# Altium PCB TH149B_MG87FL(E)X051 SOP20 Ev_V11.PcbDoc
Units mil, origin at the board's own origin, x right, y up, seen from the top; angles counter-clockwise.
Board outline 2850 x 2111 mil, 2 copper layers (Top Layer, Bottom Layer); 47 components, 39 nets, 238 pads, 92 vias.
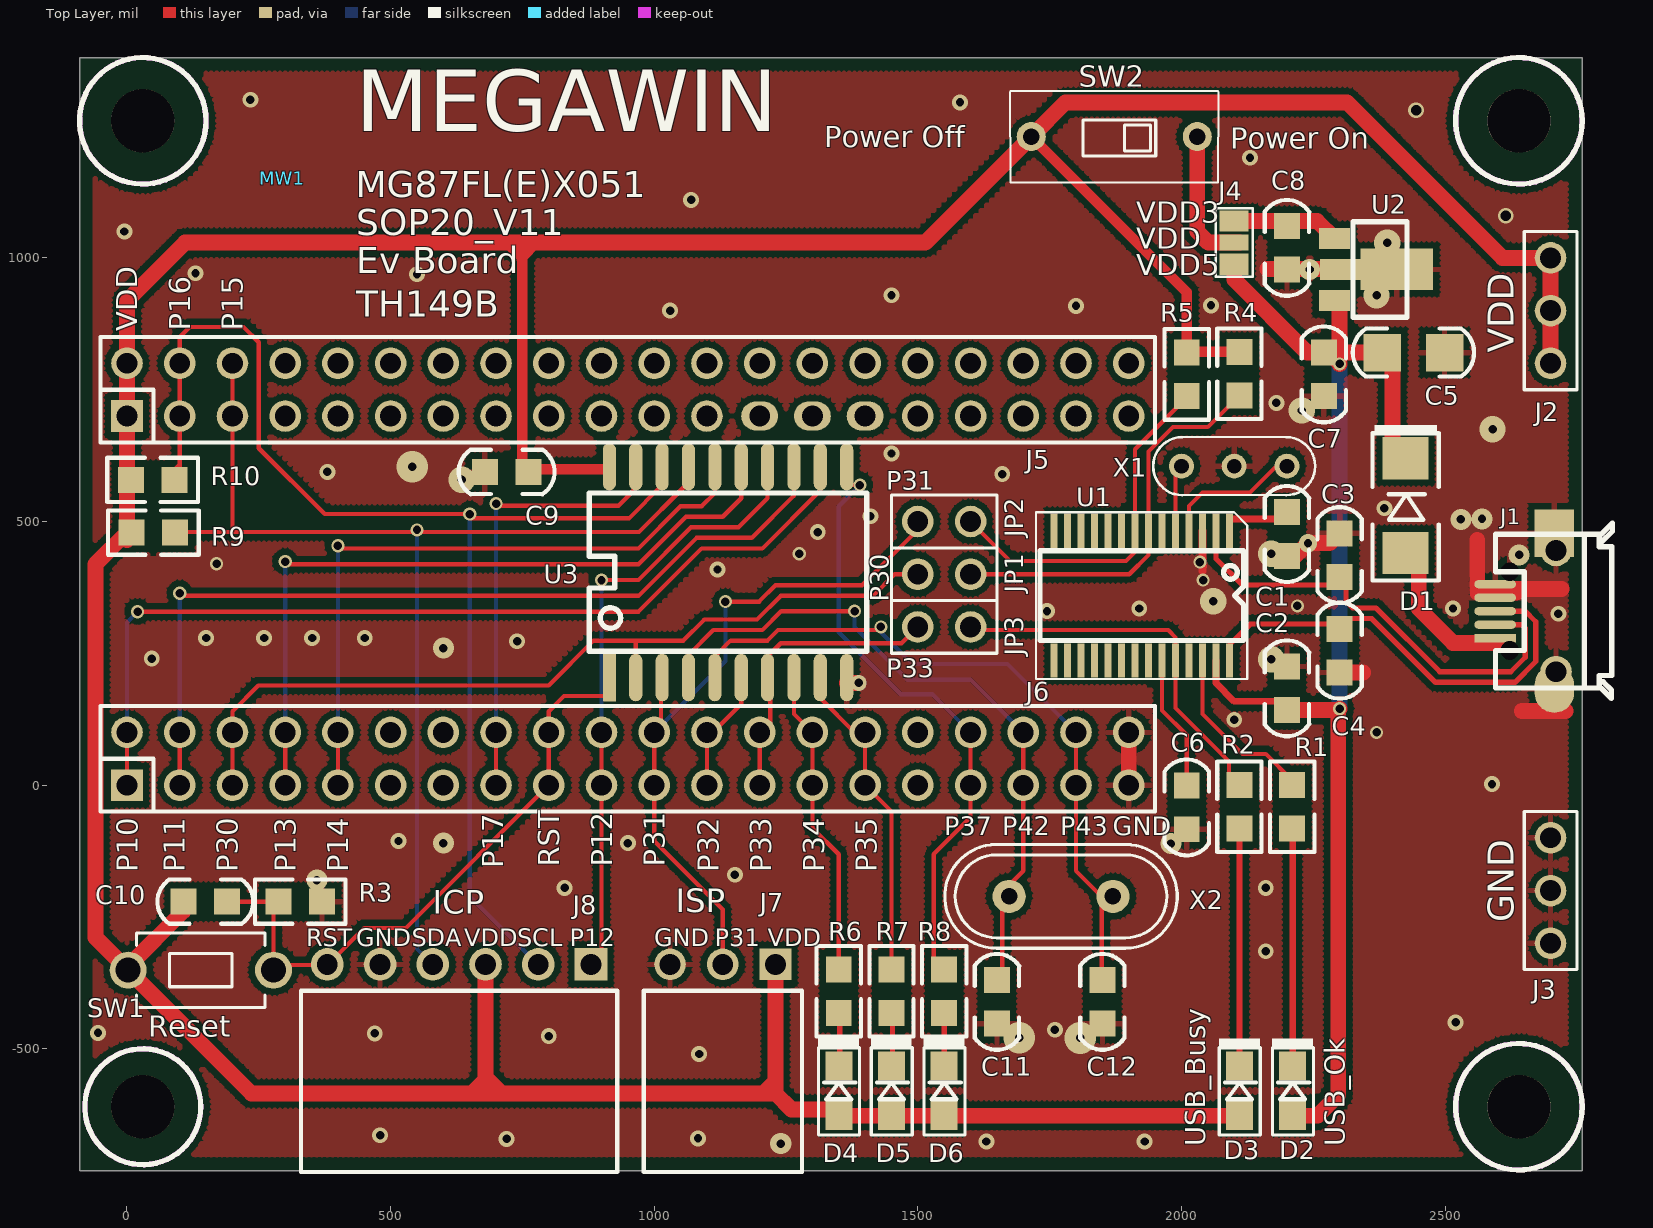
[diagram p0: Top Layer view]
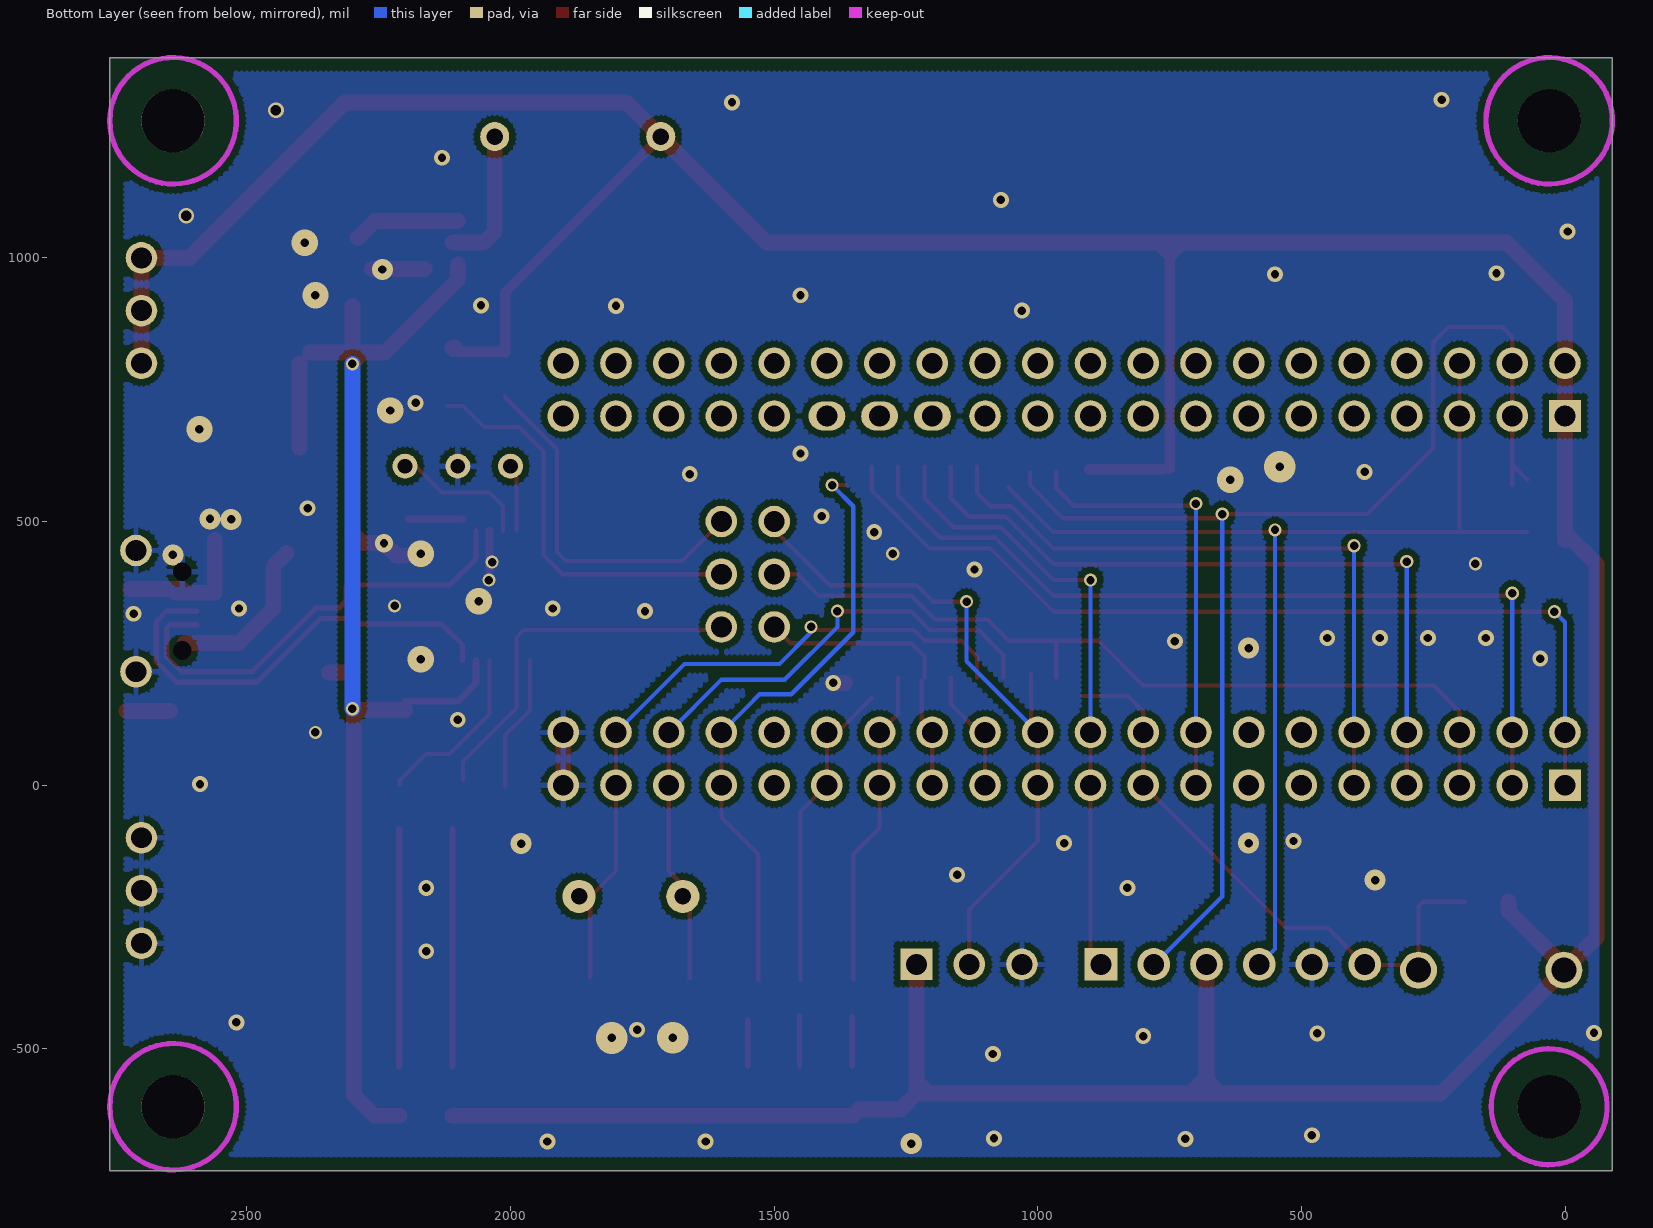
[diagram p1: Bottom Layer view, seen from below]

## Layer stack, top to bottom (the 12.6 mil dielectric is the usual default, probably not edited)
Top Layer: signal copper 1.4
Dielectric: dielectric 12.6, FR-4, Dk 4.8
Bottom Layer: signal copper 1.4

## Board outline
-90,-731 -90,1380 2760,1380 2760,-731

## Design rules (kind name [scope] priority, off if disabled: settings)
Clearance 12 [All] p1 off: gap=12
Clearance 10 [All] p2 off: gap=10
Clearance 6 [All] p3: gap=6
ComponentClearance [All] p1 off: gap=10 collisioncheckmode=3 verticalgap=10 showdistances=FALSE
HoleSize [All] p1: absolutevalues=TRUE maxlimit=500 minlimit=1 maxpercent=80.000 minpercent=20.000
MinimumSolderMaskSliver [All] p1 off: minsoldermaskwidth=10
PolygonConnect VIA [ISVIA] p1: connectstyle=Direct reliefconductorwidth=10 reliefentries=4 polygonreliefangle="90 Angle"
PolygonConnect [All] p2: connectstyle=Relief reliefconductorwidth=10 reliefentries=4 polygonreliefangle="90 Angle"
RoomDefinition "TH149B_MG87FL(E)X051 SOP20 Ev_V10" [InComponentClass('TH149B_MG87FL(E)X051 SOP20 Ev_V10')] p1: confinementstyle=ConfineIn formatcopy=TRUE lockcomponents=FALSE outline -775,-1340 3190,-1340 3190,1780 -775,1780
RoutingVias [All] p1: holewidth=16 width=25 viastyle="Through Hole" minholewidth=16 minwidth=24 maxholewidth=28 maxwidth=50
SilkToSilkClearance [All] p1 off: silktosilkclearance=10
SilkscreenOverComponentPads [All] p1 off: minsilkscreentomaskgap=10
SolderMaskExpansion [All] p1 off: expansion=4
Width [All] p1: maxlimit=200 minlimit=6 preferedwidth=10
23 further rules are at their usual default settings.

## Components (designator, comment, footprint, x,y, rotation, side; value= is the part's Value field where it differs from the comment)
C1 "4.7uF" 0805C 2200,476.34 r270 top
C2 "0.1uF" 0805C 2200,183.66 r270 top
C3 "15pF" 0805C 2300,436.34 r90 top
C4 "15pF" 0805C 2300,255 r270 top
C5 "4.7uF" 1206C 2440,820.34 r0 top
C6 "0.1uF" 0805C 2010,-42.34 r90 top
C7 "0.1uF" 0805C 2270,779 r270 top
C8 "4.7uF" 0805C 2200,1019 r270 top
C9 "0.1uF" 0805C 720,594 r180 top
C10 "1u" 0805C 148.66,-221 r0 top
C11 "30p" 0805C 1650,-411 r270 top
C12 "30p" 0805C 1850,-411 r270 top
D1 "1N5817" D5817_SMD_1 2425,530 r270 top
D2 "Yellow" 0805D 2210.79,-580 r90 top
D3 "RED" 0805D 2110,-580 r90 top
D4 "Green" 0805D 1350,-580 r90 top
D5 "RED" 0805D 1450,-580 r90 top
D6 "Green" 0805D 1550,-580 r90 top
J1 "Micro USB母座" JACK_USB_SMD290X220P065 2595,330 r180 top
J2 "*" PS3P254 2700,800 r90 top
J3 "*" PS3P254 2700,-100 r270 top
J4 "*" JUMP3_SMD 2100,1029 r90 top
J5 "*" PS20X2P254#1 0,700 r0 top locked
J6 "*" PS20X2P254#2 0,0 r0 top locked
J7 "*" PS3P254f_90 1230,-340 r180 top
J8 "*" PS6P254F_90 880,-340 r180 top
JP1 "JUMPER2" PS2P254 1500,400 r0 top
JP2 "JUMPER2" PS2P254 1500,500 r0 top
JP3 "JUMPER2" PS2P254 1500,300 r0 top
MW1 "MW-A4" MEGAWIN_T 294.19,1151.19 r0 top
R1 "1K" 0805R 2210,-41 r270 top
R2 "1K" 0805R 2110,-41 r270 top
R3 "47K" 0805R 328.66,-221 r180 top
R4 "4.7K" 0805R 2110,780.34 r270 top
R5 "4.7K" 0805R 2010,779 r270 top
R6 "1K" 0805R 1350,-391 r270 top
R7 "1K" 0805R 1450,-391 r270 top
R8 "1K" 0805R 1550,-391 r270 top
R9 "4.7K" 0805R 50,479 r180 top
R10 "4.7K" 0805R 48.66,579 r180 top
SW1 "SW TACT-SPST" SW_T_2P 140,-351 r180 top
SW2 "-" DIP2_SW 2030,1230 r180 top
U1 "MA101_TSSOP28" TSSOP28_170P065 1924.84,359.52 r180 top
U2 "AIC1734-33(SOT-89)" SOT89 2290,978.06 r270 top
U3 "MG87Fx6051(20-SOP)" SO20_300P127 1140,404 r0 top locked
X1 "6MHz" X3P 2200,605 r180 top
X2 "22.1184MHz" X49U 1771.57,-211 r0 top

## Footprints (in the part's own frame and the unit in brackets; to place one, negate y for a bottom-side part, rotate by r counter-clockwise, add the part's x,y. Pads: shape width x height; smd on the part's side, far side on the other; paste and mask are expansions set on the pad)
0805C [mm]
  rect 1.25x1.25 smd: 1(-1.05,0) 2(1.05,0)
  silkscreen extent -2.31,-1.07 2.31,1.07
0805D [mm]
  rect 1.4x1.3 smd: 1(-1.192,0) 2(1.192,0)
  silkscreen extent -2.12,-1 2.53,0.98
0805R [mm]
  rect 1.25x1.25 smd: 1(-1.05,0) 2(1.05,0)
  silkscreen extent -2.18,-1.07 2.18,1.07
1206C [mm]
  rect 1.8x1.8 smd: 1(-1.5,0) 2(1.5,0)
  silkscreen extent -2.92,-1.15 2.92,1.16
D5817_SMD_1 [mil]
  rect 80x86.61 smd: 1(90,0) 2(-90,0)
  silkscreen extent -153,-63 142,63
DIP2_SW [mm]
  round 1.4 hole 0.8: 1(0,0) 2(8,0)
  silkscreen extent -1.02,-2.2 9.02,2.2
JACK_USB_SMD290X220P065 [mm]
  rect 1.9x1.8 on Mech2: 0(-2.85,-1.15) 0(-2.85,1.15)
  round 0.8 hole 0.9 unplated: 1(-0.7,1.9) 5(-0.7,-1.9)
  rect 2x0.4 smd: 1(0,1.3)
  oval 2x0.4 smd: 2(0,0.65) 3(0,0) 4(0,-0.65) 5(0,-1.3)
  round 1.524 hole 1: 5(-2.931,2.921) 5(-2.931,-2.921)
  oval 1.9x2.3 smd: 5(-2.85,3.75)
  rect 1.9x2.3 smd: 5(-2.85,-3.75)
  silkscreen extent -5.65,-4.25 -0.01,4.2
JUMP3_SMD [mil]
  rect 40x55 smd: 1(-41,0) 3(41,0)
  rect 30x55 smd: 2(0,0)
  silkscreen extent -65,-35 65,35
MEGAWIN_T [mil]
PS2P254 [mil]
  round 60 hole 39.37: 1(0,0) 2(100,0)
  silkscreen extent -50,-50 150,50
PS3P254 [mil]
  round 60 hole 39.37: 1(0,0) 2(100,0) 3(200,0)
  silkscreen extent -50,-50 250,50
PS3P254f_90 [mil]
  rect 60x60 hole 39.37: 1(0,0)
  round 60 hole 39.37: 2(100,0) 3(200,0)
  silkscreen extent -50,50 250,394
PS6P254F_90 [mil]
  rect 62x62 hole 39.37: 1(0,0)
  round 62 hole 39.37: 2(100,0) 3(200,0) 4(300,0) 5(400,0) 6(500,0)
  silkscreen extent -50,50 550,394
PS20X2P254#1 [mil]
  rect 60x60 hole 39.37: 1(0,0)
  round 60 hole 39.37: 2(0,100) 3(100,0) 4(100,100) 5(200,0) 6(200,100) 7(300,0) 8(300,100) 9(400,0) 10(400,100) 11(500,0) 12(500,100) 13(600,0) 14(600,100) 15(700,0) 16(700,100) 17(800,0) 18(800,100) 19(900,0) 20(900,100) 21(1000,0) 22(1000,100) 23(1100,0) 24(1100,100) 26(1200,100) 28(1300,100) 30(1400,100) 31(1500,0) 32(1500,100) 33(1600,0) 34(1600,100) 35(1700,0) 36(1700,100) 37(1800,0) 38(1800,100) 39(1900,0) 40(1900,100)
  oval 70x55 hole 39.37: 25(1200,0) 27(1300,0) 29(1400,0)
  silkscreen extent -50,-50 1950,150
PS20X2P254#2 [mil]
  rect 60x60 hole 39.37: 1(0,0)
  round 60 hole 39.37: 2(0,100) 3(100,0) 4(100,100) 5(200,0) 6(200,100) 7(300,0) 8(300,100) 9(400,0) 10(400,100) 11(500,0) 12(500,100) 13(600,0) 14(600,100) 15(700,0) 16(700,100) 17(800,0) 18(800,100) 19(900,0) 20(900,100) 21(1000,0) 22(1000,100) 23(1100,0) 24(1100,100) 25(1200,0) 26(1200,100) 27(1300,0) 28(1300,100) 29(1400,0) 30(1400,100) 31(1500,0) 32(1500,100) 33(1600,0) 34(1600,100) 35(1700,0) 36(1700,100) 37(1800,0) 38(1800,100) 39(1900,0) 40(1900,100)
  silkscreen extent -50,-50 1950,150
SO20_300P127 [mil]
  rect 25x90 smd: 1(-225,-200)
  oval 25x90 smd: 2(-175,-200) 3(-125,-200) 4(-75,-200) 5(-25,-200) 6(25,-200) 7(75,-200) 8(125,-200) 9(175,-200) 10(225,-200) 11(225,200) 12(175,200) 13(125,200) 14(75,200) 15(25,200) 16(-25,200) 17(-75,200) 18(-125,200) 19(-175,200) 20(-225,200)
  silkscreen extent -263,-150 263,150
SOT89 [mm]
  rect 1.016x1.5 smd: 1(-1.5,0) 3(1.5,0)
  rect 2x3.5 smd: 2(0,3)
  rect 1.016x2.6 smd: 2(0,0.6)
  silkscreen extent -2.3,0.9 2.3,3.5
SW_T_2P [mil]
  round 70 hole 47.24: 1(-137.79,0) 2(137.79,0)
  silkscreen extent -122,-71 122,71
TSSOP28_170P065 [mil]
  rect 13x65 smd: 1(-166.34,-123) 2(-140.75,-123) 3(-115.16,-123) 4(-89.57,-123) 5(-63.98,-123) 6(-38.39,-123) 7(-12.79,-123) 8(12.8,-123) 9(38.39,-123) 10(63.98,-123) 11(89.57,-123) 12(115.16,-123) 13(140.75,-123) 14(166.34,-123) 15(166.34,123) 16(140.75,123) 17(115.16,123) 18(89.57,123) 19(63.98,123) 20(38.39,123) 21(12.8,123) 22(-12.79,123) 23(-38.39,123) 24(-63.98,123) 25(-89.57,123) 26(-115.16,123) 27(-140.75,123) 28(-166.34,123)
  silkscreen extent -200,-158 201,158
X3P [mm]
  round 1.2 hole 0.711: 1(0,0) 2(5.08,0) 3(2.54,0)
  silkscreen extent -1.36,-1.4 6.44,1.4
X49U [mm]
  round 1.6 hole 0.8: 1(-2.5,0) 2(2.5,0)
  silkscreen extent -5.6,-2.5 5.6,2.5

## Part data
C1 C5 C8: library part CAP
C2 C3 C4 C6 C7 C9: library part "CAP NP"
C10: library part C
C11 C12: library part "C NP"
D1: library part DIODE_ZD, "Schottky Diode"
D2 D3 D4 D5 D6: library part LED
J1: library part CON5, "Connector"
J2 J3 J4 J7: library part CON3
J5 J6: library part CON40A
J8: library part CON6
R1 R2 R4 R5 R6 R7 R8: library part R_Dup1
R3 R9 R10: library part R
SW2: library part SW-2
U2: library part AIC1734-33(SOT-89)_0
U3: library part MPC82L52(20-DIP)
X1: library part CRYSTAL_RC
X2: library part CRYSTAL

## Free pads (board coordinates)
  round 120 hole 120 unplated: 0(30,-610) 0(30,1260) 0(2640,-610) 0(2640,1260)

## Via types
v1: diameter 30, hole 16, Top Layer to Bottom Layer, tented both sides, 49 vias
v2: diameter 25, hole 16, Top Layer to Bottom Layer, tented both sides, 20 vias
v3: diameter 50, hole 16, Top Layer to Bottom Layer, tented both sides, 8 vias
v4: diameter 40, hole 16, Top Layer to Bottom Layer, tented both sides, 7 vias
v5: diameter 60, hole 16, Top Layer to Bottom Layer, tented both sides, 3 vias
v6: diameter 39.37, hole 16, Top Layer to Bottom Layer, tented both sides, 2 vias
v7: diameter 30, hole 20, Top Layer to Bottom Layer, tented both sides, 2 vias
v8: diameter 35, hole 16, Top Layer to Bottom Layer, tented both sides, 1 vias

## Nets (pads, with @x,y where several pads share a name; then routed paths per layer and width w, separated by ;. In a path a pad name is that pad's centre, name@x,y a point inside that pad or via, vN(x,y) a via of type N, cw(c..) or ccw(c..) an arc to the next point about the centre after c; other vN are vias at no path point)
D+: C4.1 J1.3 U1.28 | length 842.2
  Top Layer w10: U1.28 2091.18,266.18 2130.67,305.67 C4.1@2300,305.67 ; C4.1@2312,316 2360.72,316 2481.72,195 2632.72,195 2672,234.28 2672,309.93 2651.93,330 J1.3
D-: C3.1 J1.2 U1.2 | length 857.2
  Top Layer w10: U1.2 2065.59,429.41 2115.63,379.37 C3.1@2300,379.37 ; C3.1@2312,376 2312,349 2325,336 2369,336 2490,215 2624.44,215 2652,242.56 2652,297.84 2645.43,304.41 J1.2
GND_POWER: C1.2 C2.1 C3.2 C4.2 C5.2 C6.1 C7.2 C8.2 C9.2 C11.2 C12.2 J1.4 J1.5 J3.1 J3.2 J3.3 J6.39 J6.40 J7.3 J8.5 R3.1 U1.3 U2.2 U3.10 X1.3 | length 814
  Top Layer w15: 2040,406 v2@2040,416 ; U1.3 v2@2040,416 ; v2@2041,415 v2@2040,416
  Top Layer w30: U3.10@1365,194 v1(1388,194) ; J6.39 J6.40 ; 2163.39,979 U2.2@2263,979 ; C1.2 2216,435 v8(2240,459) 2281.32,459 C3.2 ; C4.2 2344.66,213.66 ; 2560.87,365.05 2634.29,365.05 ; 2560.87,367.64 2560.87,464.72 ; 2623.54,372.05 2720.63,372.05 ; 2645.28,140.87 2728.82,140.87
  other v1: 1630,-675.92 1930,-675.92 720,-671 1083,-670 480,-664 1085,-510 800,-476 470,-471 -55,-470 1760,-464 2520,-450 2160,-315 830,-195 2160,-195 1153,-170 950,-110 515,-106 2589,2 2100,124 47,240 740,273 150,279 260,279 351,279 451,279 2715,325 1745,330 1920,335 2515,335 1120,409 1310,480 1410,510 2385,525 1660,590 380,594 1450,629 2180,725 1030,900 1800,909 2056,910 1450,929 550,969 130,971 -5,1050 1070,1110 2130,1190 1580,1295 234,1300
  other v2: 2370,100 2220,340 2041,389 170,420 2035,423 1275,439
  other v3: 2170,239 2060,349 2170,439 635,579 2590,675 2228,710.5 2370,929 2390,1029
  other v4: 1240,-680 360,-180 1980,-111 600,-110 600,260 2640.29,436.72 2243,978
  other v5: 1808,-479.5 1692,-478.83 541,604
  other v6: 2530,504 2570,505
  other v7: 2615,1080 2445,1280
MA101_RX: JP2.2 R5.2 U1.8 | length 686.4
  Top Layer w8: JP2.2 1675,425 1895,425 1912.05,442.05 U1.8 1912.05,637.05 2010,735 R5.2
MA101_TX: JP1.2 R4.2 U1.7 | length 766.9
  Top Layer w8: JP1.2 1901,400 1937.64,436.64 1937.64,632.64 1984,679 2050,679 2090,719 R4.2@2120,719
NetC1_1: C1.1 U1.1 | length 102.5
  Top Layer w13: U1.1@2091.18,505 C1.1@2193.66,505
NetC6_2: C6.2 U1.23 | length 269.1
  Top Layer w8: 1963.23,191.18 1963.23,179 ; U1.23 1963.23,179 ; C6.2 2010,95 1963.23,141.77 1963.23,179
NetD1_1: D1.1 J1.1 | length 309.6
  Top Layer w30: D1.1 2450,415 2450,335 2515.28,269.72 J1.1@2617.2,269.72
NetD2_2: D2.2 R1.2 | length 450
  Top Layer w12: D2.2 R1.2@2210.79,-83.13
NetD3_2: D3.2 R2.2 | length 450.7
  Top Layer w12: D3.2 R2.2
NetD4_2: D4.2 R6.2 | length 95.1
  Top Layer w10: D4.2@1352,-533.08 R6.2@1352,-437.93
NetD5_2: D5.2 R7.2 | length 96.5
  Top Layer w10: D5.2@1452,-533.08 R7.2@1452,-436.59
NetD6_2: D6.2 R8.2 | length 88.1
  Top Layer w10: D6.2 R8.2@1550,-445
NetJ4_2: J4.2 SW2.1 | length 268.7
  Top Layer w30: SW2.1 2030,1050 2051,1029 J4.2 J4.2@2110,1029
NetU1_4: U1.4 X1.1 | length 263.8
  Top Layer w8: U1.4 2014.41,529.41 2040,555 2130,555 2180,605 X1.1
NetU1_5: U1.5 X1.2 | length 127.1
  Top Layer w8: U1.5 1988.82,593.82 X1.2
P10: J6.1 J6.2 U3.12 | length 1772.6
  Top Layer w8: J6.1 J6.2 ; v2(20,329) 970,329 1090,449 1205,449 1315,559 U3.12
  Bottom Layer w8: J6.2 0,309 v2(20,329)
P11: J6.3 J6.4 U3.13 | length 1662.7
  Top Layer w8: J6.3 J6.4 ; v2@100,359 970,359 1080,469 1185,469 1265,549 U3.13
  Bottom Layer w8: J6.4 v2(100,364)
P12: J6.19 J6.20 J8.1 U3.14 | length 1149.2
  Top Layer w8: J8.1@900,-321 J6.19 J6.20 ; v2(900,389) 970,389 1070,489 1160,489 1215,544 U3.14
  Bottom Layer w8: J6.20 v2(900,389)
P13: J6.7 J6.8 U3.15 | length 1400.8
  Top Layer w8: J6.7 J6.8 ; v2@300,419 970,419 1060,509 1130,509 1165,544 U3.15
  Bottom Layer w8: J6.8 v2(300,424)
P14: J6.9 J6.10 U3.16 | length 1262.5
  Top Layer w8: J6.9 J6.10 ; v2@400,449 970,449 1050,529 1090,529 1115,554 U3.16
  Bottom Layer w8: J6.10 v2(400,454)
P15: J5.5 J5.6 J8.4 R9.1 U3.17 | length 2172.3
  Top Layer w8: R9.1@71.34,479 72.34,480 200,480 ; J5.6 J5.5 200,480 ; 1055,564 971,480 200,480
  Bottom Layer w8: v2@550,480 550,-311 J8.4@580,-341
  other v2: 550,484
P16: J5.3 J5.4 J8.2 R10.1 U3.18 | length 2549.4
  Top Layer w8: R10.1@71.34,579 100,607.66 ; R10.1@100,569 100,607.66 ; 600,514 515,514 ; U3.18@1015,594 1015,569 952,506 650,506 642,514 515,514 ; 100,607.66 J5.3 J5.4 100,850 119,869 221,869 250,840 250,639 375,514 515,514
  Bottom Layer w8: v2@650,506 650,-211 J8.2@780,-341
  other v2: 650,514
P17: J6.15 J6.16 U3.19 | length 839.7
  Top Layer w8: J6.15 J6.16 ; v2@700,530 932,530 965,563 U3.19@965,594
  Bottom Layer w8: J6.16 v2@700,530
  other v2: 700,534
P30_RXD: J6.5 J6.6 JP1.1 U3.2 | length 1617.7
  Top Layer w8: J6.5 J6.6 200,140 249,189 800,189 885,274 965,274 ; U3.2 965,274 ; JP1.1 1456,400 1415,359 1240,359 1195,314 1095,314 1055,274 965,274
P31_TXD: J6.21 J6.22 J7.2 JP2.1 U3.3 | length 1348.7
  Top Layer w8: J6.22@1005,105 J6.22 J6.21 1000,-106 1130,-236 J7.2 J7.2@1130,-341 ; J6.22@1012.6,112.6 U3.3@1012.6,211.6 ; J7.2@1110,-331 J7.2@1115,-326 ; v2(1135,348) 1199,348 1230,379 1394,379 1500,485 JP2.1
  Bottom Layer w8: J6.22 1135,235 v2(1135,348)
P32: J6.23 J6.24 U3.6 | length 237.4
  Top Layer w8: J6.23 J6.24 1111,100 1165,154 U3.6
P33: J6.25 J6.26 JP3.1 U3.7 | length 554.3
  Top Layer w8: J6.25 J6.26 J6.26@1205,105 ; U3.7 1215,244 1240,269 1469,269 JP3.1 ; J6.26@1220,99 U3.7@1220,198
P34: J6.27 J6.28 R6.1 U3.8 | length 608.9
  Top Layer w8: U3.8 1265,135 J6.28 J6.27 1300,-81 1350,-131 R6.1 R6.1@1350,-369.66
P35: J6.29 J6.30 R7.1 U3.9 | length 602.3
  Top Layer w8: U3.9@1315,165 1380,100 J6.30 J6.29 1450,-50 R7.1 R7.1@1450,-369.66
P37: J6.33 J6.34 R8.1 U3.11 | length 1186.2
  Top Layer w8: U3.11@1365,569 v2(1390,569) ; R8.1@1530,-369.66 1530,-131 1600,-61 J6.33 J6.34 J6.34@1600,109
  Bottom Layer w8: v2(1390,569) 1350,529 1350,290 1467.55,172.45 1527.55,172.45 1550.73,149.27 ; 1530,170 1550.73,149.27 ; J6.34 1550.73,149.27
P42: C11.1 J6.35 J6.36 U3.4 X2.1 | length 1294.2
  Top Layer w8: U3.4 1065,247 1112,294 1205,294 1241,330 v2(1380,330) ; C11.1@1660,-366 X2.1@1660,-212.85 ; X2.1@1662.36,-200.21 1700,-162.58 J6.35 J6.36
  Bottom Layer w8: v2(1380,330) 1380,300 1480,200 1600,200 J6.36
P43: C12.1 J6.37 J6.38 U3.5 X2.2 | length 1313.6
  Top Layer w8: U3.5 1115,244 1145,274 1215,274 1235,294 v2@1424,294 ; J6.38 J6.37 1800,-162.58 1848.66,-211.24 C12.1@1848.66,-365
  Bottom Layer w8: v2(1430,300) 1430,290 1490,230 1670,230 J6.38
RST: C10.2 J6.17 J6.18 J8.6 R3.2 SW1.1 U3.1 | length 1132.7
  Top Layer w8: C10.2 268.27,-221 277.79,-230.53 SW1.1 ; SW1.1@287.79,-341 380,-341 450,-271 529,-271 J6.17 J6.18 800,140 829,169 U3.1@915,169
USB_BUSY: JP3.2 R2.1 U1.24 | length 839.6
  Top Layer w8: JP3.2@1606,294 1720,294 ; 1710,294 1720,294 ; 2080,55 1988.82,146.18 ; R2.1@2090,10 2090,45 1988.82,146.18 ; 1720,294 1975,294 1988.82,280.18 U1.24 1988.82,146.18
USB_OK: R1.1 U1.26 | length 344.6
  Top Layer w8: 2040,191.18 2040,179 ; U1.26 2040,179 ; R1.1 2210,9 2160,59 2116,59 2040,135 2040,179
VDD: C9.1 C10.1 D3.1 D4.1 D5.1 D6.1 J2.1 J2.2 J2.3 J5.1 J5.2 J7.1 J8.3 R4.1 R5.1 R9.2 R10.2 SW1.2 SW2.2 U3.20 | length 8878.8
  Top Layer w15: 644,-584.9 680,-548.9 681,-547.9 ; 684,-547.9 721,-584.9 ; 712,1034 717,1029 748.5,997.5 ; 748,997 748.5,997.5 ; 749,997 748.5,997.5 ; 785,1034 780,1029 750,999 749,998 748.5,997.5 ; 1193,-588 1196.1,-584.9 1230,-551
  Top Layer w20: 749,997 749,998 749,1029 ; C9.1@750,600 750,999 750,1029 ; C9.1@761.34,599 902,599 ; SW2.2 2010,935.04 R5.1 ; R5.1@2011.34,821.68 R4.1
  Top Layer w30: R9.2@0,465 R9.2@0,479 ; SW1.2@2.21,-343.79 107.32,-238.68 C10.1 ; 383.9,-584.9 390,-584.9 ; J8.3@680,-341 680,-548.9 680,-584.9 ; J7.1@1230,-341 1230,-551 1230,-584.9 ; D4.1@1340,-615 1260.1,-615 1230,-584.9 ; D4.1 D5.1 D6.1 D3.1 ; R4.1@2104.95,829 R4.1@2110,829 ; J2.1 J2.2 J2.3 2609,1000 2314,1295 1780.04,1295 SW2.2 1514.04,1029 780,1029 750,1029 749,1029 717,1029 110,1029 0,919 J5.2 J5.1 R9.2@0,479 ; R9.2@0,479 -60,419 -60,-288.79 SW1.2 236.1,-584.9 390,-584.9 ; 390,-584.9 644,-584.9 680,-584.9 ; 680,-584.9 721,-584.9 1196.1,-584.9 1230,-584.9
VDD3: C8.1 J4.3 U2.1 | length 203.6
  Top Layer w30: J4.3 2257.11,1070 U2.1
VDD5: C2.2 C5.1 C7.1 D1.2 D2.1 J4.1 U1.27 U2.3 | length 2426
  Top Layer w13: U1.27 2065.59,193.41 2100,159 C2.2@2200,159
  Top Layer w30: J4.1 2100,959 2238.66,820.34 C7.1@2268.66,820.34 ; C2.2 v2@2297.32,142.32 ; D2.1 2258.08,-626.92 2297.32,-587.68 v2@2297.32,142.32 ; C7.1@2269.33,819.67 C7.1@2268.66,820.34 ; v2(2300,145) v2@2297.32,142.32 ; v2(2300,799) 2300,800.34 C7.1@2280,820.34 ; U2.3@2300,909 2300,820.34 ; C5.1 2300,820.34 ; D1.2@2400,640 C5.1@2400,799.72 ; C7.1@2268.66,820.34 C7.1 C7.1@2280,820.34 ; C7.1@2280,820.34 2300,820.34
  Bottom Layer w30: v2(2300,145) v2(2300,799)
pads on no net: J1.0 J5.7 J5.8 J5.9 J5.10 J5.11 J5.12 J5.13 J5.14 J5.15 J5.16 J5.17 J5.18 J5.19 J5.20 J5.21 J5.22 J5.23 J5.24 J5.25 J5.26 J5.27 J5.28 J5.29 J5.30 J5.31 J5.32 J5.33 J5.34 J5.35 J5.36 J5.37 J5.38 J5.39 J5.40 J6.11 J6.12 J6.13 J6.14 J6.31 J6.32 U1.6 U1.9 U1.10 U1.11 U1.12 U1.13 U1.14 U1.15 U1.16 U1.17 U1.18 U1.19 U1.20 U1.21 U1.22 U1.25

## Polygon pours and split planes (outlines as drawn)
GND_POWER on Top Layer "Bottom Layer-No Net" (hatched 90Degree grid 10 track 10, remove dead copper, pour order 1001): -60,-701 2730,-701 2730,1350 -60,1350
GND_POWER on Bottom Layer "Bottom Layer-No Net" (hatched 90Degree grid 10 track 10, remove dead copper, pour order 1001): -60,-701 2730,-701 2730,1350 -60,1350

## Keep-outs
Keep-Out Layer:
  circle w10: c2640,1260 r120
  circle w10: c30,-610 r110
  circle w10: c30,1260 r120
  circle w10: c2640,-610 r120

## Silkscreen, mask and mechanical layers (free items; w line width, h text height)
Top Overlay:
  circle w10: c2640,1260 r120
  circle w10: c30,-610 r110
  circle w10: c30,1260 r120
  circle w10: c2640,-610 r120
  text "Power Off" at 1322.62,1210 h40
  text "Power On" at 2092.62,1207 h40
  text "MG87FL(E)X051" at 434.19,1115.19 h50
  text "VDD3" at 1914.25,1067 h40
  text "SOP20_V11" at 435,1043 h50
  text "VDD" at 1914.25,1017 h40
  text "Ev Board" at 435,971 h50
  text "VDD5" at 1914.25,967 h40
  text "TH149B" at 435,888 h50
  text "P16" at 120,862 h40 r90
  text "P15" at 220,862 h40 r90
  text "VDD" at 19,861 h40 r90
  text "VDD" at 2630,820 h50 r90
  text "P31" at 1440,560 h35
  text "P30" at 1445,348 h35 r90
  text "P33" at 1440,205 h35
  text "P37" at 1550,-95 h35
  text "P42" at 1660,-95 h35
  text "P43" at 1770,-95 h35.43
  text "GND" at 1870,-95 h35.43
  text "RST" at 820,-155 h40 r90
  text "P12" at 920,-155 h40 r90
  text "P31" at 1020,-155 h40 r90
  text "P17" at 713.95,-158.05 h40 r90
  text "P10" at 20,-165 h40 r90
  text "P11" at 110,-165 h40 r90
  text "P30" at 210,-165 h40 r90
  text "P13" at 320,-165 h40 r90
  text "P14" at 420,-165 h40 r90
  text "P32" at 1122,-165 h40 r90
  text "P33" at 1222,-165 h40 r90
  text "P34" at 1322,-165 h40 r90
  text "P35" at 1422,-165 h40 r90
  text "ISP" at 1041,-241 h45
  text "ICP" at 580,-244 h45
  text "GND" at 2630,-260 h50 r90
  text "RST" at 340,-306 h33
  text "GND" at 435,-306 h33
  text "SDA" at 540,-306 h33
  text "VDD" at 640,-306 h33
  text "SCL" at 740,-306 h33
  text "P12" at 840,-306 h33
  text "GND" at 1000,-306 h33
  text "P31" at 1115,-306 h33
  text "VDD" at 1215,-306 h33
  text "Reset" at 40,-477 h40
  text "USB_Busy" at 2045,-685 h38 r90
  text "USB_Ok" at 2310,-685 h38 r90
Mechanical 1:
  the board outline again, w13

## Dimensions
-90,1380 to -90,-731 on Top Overlay
-90,-731 to 2760,-731 on Top Overlay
